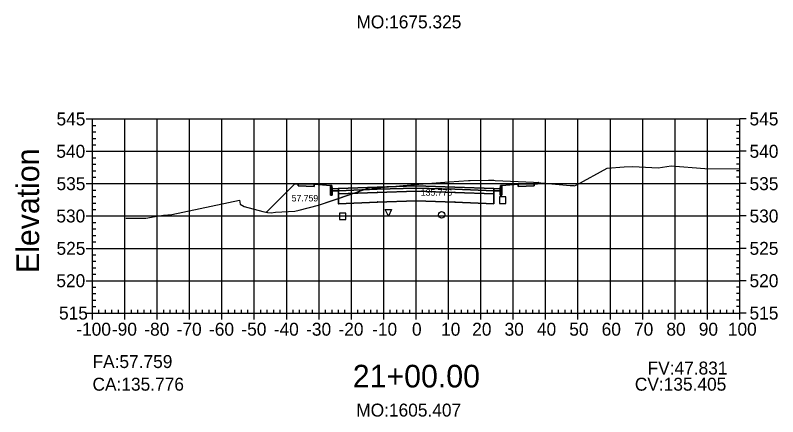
# Model space of a CAD drawing. Extents: x 704834 to 709892, y 372981 to 377533.
# Drawn here: x 705463 to 705698.6, y 373570.8 to 373694.9 of the extents above; entities that cross this region are included whole.
import ezdxf

# ---------------------------------------------------------------- set-up
doc = ezdxf.new("R2010")
doc.units = 0
for name, color, linetype in [('1', 7, 'Continuous'), ('10', 7, 'Continuous'), ('13', 7, 'Continuous'), ('14', 7, 'Continuous'), ('4', 7, 'Continuous'), ('57', 7, 'Continuous'), ('59', 7, 'Continuous'), ('60', 7, 'Continuous'), ('Default_Xsect', 7, 'Continuous'), ('Existing', 7, 'Continuous')]:
    doc.layers.add(name, color=color, linetype=linetype)

msp = doc.modelspace()

# ---------------------------------------------------------------- linework, layer by layer
for points in [[(705549.37, 373642.77), (705540.61, 373634)], [(705550.37, 373642.81), (705549.37, 373642.77)], [(705623.37, 373642.81), (705624.37, 373642.77)], [(705624.37, 373642.77), (705624.76, 373643.16)], [(705560.37, 373642.21), (705555.37, 373642.61)], [(705613.37, 373642.21), (705618.37, 373642.61)]]:
    msp.add_lwpolyline(points)
for points in [[(705555.37, 373642.61), (705550.37, 373642.81), (705550.37, 373642.15), (705555.37, 373641.95)], [(705618.37, 373641.95), (705623.37, 373642.15), (705623.37, 373642.81), (705618.37, 373642.61)], [(705560.87, 373641.21), (705560.79, 373642.21), (705560.37, 373642.21), (705560.37, 373639.21), (705560.87, 373639.21)], [(705562.87, 373641.29), (705560.87, 373641.21), (705560.87, 373640.55), (705562.87, 373640.63)], [(705586.87, 373641.47), (705598.87, 373641.11), (705610.87, 373640.63), (705610.87, 373641.29), (705598.87, 373641.77), (705586.87, 373642.13), (705574.87, 373641.77), (705562.87, 373641.29), (705562.87, 373640.63), (705574.87, 373641.11)], [(705586.87, 373640.47), (705598.87, 373640.11), (705610.87, 373639.63), (705610.87, 373640.63), (705598.87, 373641.11), (705586.87, 373641.47), (705574.87, 373641.11), (705562.87, 373640.63), (705562.87, 373639.63), (705574.87, 373640.11)], [(705586.87, 373637.47), (705598.87, 373637.11), (705610.87, 373636.63), (705610.87, 373639.63), (705598.87, 373640.11), (705586.87, 373640.47), (705574.87, 373640.11), (705562.87, 373639.63), (705562.87, 373636.63), (705574.87, 373637.11)], [(705586.82, 373641.42), (705586.92, 373641.42), (705586.92, 373641.52), (705586.82, 373641.52)], [(705586.82, 373640.42), (705586.92, 373640.42), (705586.92, 373640.52), (705586.82, 373640.52)], [(705610.87, 373640.63), (705612.87, 373640.55), (705612.87, 373641.21), (705610.87, 373641.29)], [(705612.87, 373639.21), (705613.37, 373639.21), (705613.37, 373642.21), (705612.96, 373642.21), (705612.87, 373641.21)], [(705562.82, 373639.58), (705562.92, 373639.58), (705562.92, 373639.68), (705562.82, 373639.68)], [(705574.82, 373640.06), (705574.92, 373640.06), (705574.92, 373640.16), (705574.82, 373640.16)], [(705598.82, 373640.06), (705598.92, 373640.06), (705598.92, 373640.16), (705598.82, 373640.16)], [(705610.82, 373639.58), (705610.92, 373639.58), (705610.92, 373639.68), (705610.82, 373639.68)], [(705562.82, 373636.58), (705562.92, 373636.58), (705562.92, 373636.68), (705562.82, 373636.68)], [(705574.82, 373637.06), (705574.92, 373637.06), (705574.92, 373637.16), (705574.82, 373637.16)], [(705586.82, 373637.42), (705586.92, 373637.42), (705586.92, 373637.52), (705586.82, 373637.52)], [(705598.82, 373637.06), (705598.92, 373637.06), (705598.92, 373637.16), (705598.82, 373637.16)], [(705610.82, 373636.58), (705610.92, 373636.58), (705610.92, 373636.68), (705610.82, 373636.68)]]:
    msp.add_lwpolyline(points, close=True)
at = {"layer": '1'}
for points in [[(705540.61, 373634), (705540.9, 373633.95), (705542.05, 373633.75), (705543.42, 373633.99), (705549.39, 373634.36), (705550.74, 373634.62), (705556.73, 373636.21), (705562.87, 373638.28), (705562.87, 373639.63), (705562.87, 373640.63), (705560.87, 373640.55), (705560.87, 373639.21), (705560.37, 373639.21), (705560.37, 373642.21), (705555.37, 373642.61), (705555.37, 373641.95), (705550.37, 373642.15), (705550.37, 373642.81), (705549.37, 373642.77)], [(705562.87, 373638.28), (705570.86, 373640.97), (705573, 373641.76), (705573.32, 373641.44), (705573.38, 373641.38), (705574.82, 373641.5), (705586.37, 373642.55), (705597.05, 373643.35), (705603.06, 373643.76), (705603.39, 373643.8), (705603.55, 373643.82), (705609.22, 373643.89), (705609.3, 373643.9), (705609.63, 373643.94), (705610.87, 373643.86), (705611.26, 373643.82), (705623.11, 373643.31), (705624.76, 373643.16), (705624.37, 373642.77), (705623.37, 373642.81), (705623.37, 373642.15), (705618.37, 373641.95), (705618.37, 373642.61), (705613.37, 373642.21), (705613.37, 373639.21), (705612.87, 373639.21), (705612.87, 373640.55), (705610.87, 373640.63), (705610.87, 373639.63), (705610.87, 373636.63), (705598.87, 373637.11), (705586.87, 373637.47), (705574.87, 373637.11), (705562.87, 373636.63)], [(705578.29, 373632.81), (705577.29, 373634.81), (705579.29, 373634.81)]]:
    msp.add_lwpolyline(points, close=True, dxfattribs=at)
at = {"layer": '10'}
msp.add_lwpolyline([(705563.16, 373631.72), (705565.16, 373631.72), (705565.16, 373633.72), (705563.16, 373633.72)], close=True, dxfattribs=at)
at = {"layer": '13'}
msp.add_circle((705594.75, 373633.18), 1, dxfattribs=at)
at = {"layer": '14'}
for points in [[(705624.76, 373643.16), (705624.76, 373643.21), (705624.76, 373643.16), (705624.71, 373643.16), (705624.76, 373643.16), (705624.76, 373643.11), (705624.76, 373643.16), (705624.81, 373643.16)], [(705562.87, 373641.29), (705562.87, 373641.34), (705562.87, 373641.29), (705562.82, 373641.29), (705562.87, 373641.29), (705562.87, 373641.24), (705562.87, 373641.29), (705562.92, 373641.29)], [(705574.87, 373641.77), (705574.87, 373641.82), (705574.87, 373641.77), (705574.82, 373641.77), (705574.87, 373641.77), (705574.87, 373641.72), (705574.87, 373641.77), (705574.92, 373641.77)], [(705586.87, 373642.13), (705586.87, 373642.18), (705586.87, 373642.13), (705586.82, 373642.13), (705586.87, 373642.13), (705586.87, 373642.08), (705586.87, 373642.13), (705586.92, 373642.13)], [(705598.87, 373641.77), (705598.87, 373641.82), (705598.87, 373641.77), (705598.82, 373641.77), (705598.87, 373641.77), (705598.87, 373641.72), (705598.87, 373641.77), (705598.92, 373641.77)], [(705610.87, 373641.29), (705610.87, 373641.34), (705610.87, 373641.29), (705610.82, 373641.29), (705610.87, 373641.29), (705610.87, 373641.24), (705610.87, 373641.29), (705610.92, 373641.29)], [(705540.61, 373634), (705540.61, 373634.05), (705540.61, 373634), (705540.56, 373634), (705540.61, 373634), (705540.61, 373633.95), (705540.61, 373634), (705540.66, 373634)]]:
    msp.add_lwpolyline(points, dxfattribs=at)
at = {"layer": '4'}
msp.add_lwpolyline([(705612.61, 373636.72), (705614.61, 373636.72), (705614.61, 373638.72), (705612.61, 373638.72)], close=True, dxfattribs=at)
at = {"layer": '57'}
for p, q in [((705484.87, 373662.82), (705486.87, 373662.82)), ((705486.87, 373662.82), (705686.87, 373662.82)), ((705486.87, 373602.82), (705486.87, 373662.82)), ((705486.87, 373602.82), (705486.87, 373662.82)), ((705496.87, 373602.82), (705496.87, 373662.82)), ((705506.87, 373602.82), (705506.87, 373662.82)), ((705516.87, 373602.82), (705516.87, 373662.82)), ((705526.87, 373602.82), (705526.87, 373662.82)), ((705536.87, 373602.82), (705536.87, 373662.82)), ((705546.87, 373602.82), (705546.87, 373662.82)), ((705556.87, 373602.82), (705556.87, 373662.82)), ((705566.87, 373602.82), (705566.87, 373662.82)), ((705576.87, 373602.82), (705576.87, 373662.82)), ((705586.87, 373602.82), (705586.87, 373662.82)), ((705596.87, 373602.82), (705596.87, 373662.82)), ((705606.87, 373602.82), (705606.87, 373662.82)), ((705616.87, 373602.82), (705616.87, 373662.82)), ((705626.87, 373602.82), (705626.87, 373662.82)), ((705636.87, 373602.82), (705636.87, 373662.82)), ((705646.87, 373602.82), (705646.87, 373662.82)), ((705656.87, 373602.82), (705656.87, 373662.82)), ((705666.87, 373602.82), (705666.87, 373662.82)), ((705676.87, 373602.82), (705676.87, 373662.82)), ((705686.87, 373602.82), (705686.87, 373662.82)), ((705686.87, 373602.82), (705686.87, 373662.82)), ((705688.87, 373662.82), (705686.87, 373662.82)), ((705486.87, 373660.82), (705487.87, 373660.82)), ((705686.87, 373660.82), (705685.87, 373660.82)), ((705486.87, 373658.82), (705487.87, 373658.82)), ((705686.87, 373658.82), (705685.87, 373658.82)), ((705486.87, 373656.82), (705487.87, 373656.82)), ((705486.87, 373654.82), (705487.87, 373654.82)), ((705686.87, 373656.82), (705685.87, 373656.82)), ((705686.87, 373654.82), (705685.87, 373654.82)), ((705484.87, 373652.82), (705486.87, 373652.82)), ((705486.87, 373652.82), (705686.87, 373652.82)), ((705688.87, 373652.82), (705686.87, 373652.82)), ((705486.87, 373650.82), (705487.87, 373650.82)), ((705686.87, 373650.82), (705685.87, 373650.82)), ((705486.87, 373648.82), (705487.87, 373648.82)), ((705686.87, 373648.82), (705685.87, 373648.82)), ((705486.87, 373646.82), (705487.87, 373646.82)), ((705686.87, 373646.82), (705685.87, 373646.82)), ((705484.87, 373642.82), (705486.87, 373642.82)), ((705486.87, 373644.82), (705487.87, 373644.82)), ((705486.87, 373642.82), (705686.87, 373642.82)), ((705686.87, 373644.82), (705685.87, 373644.82)), ((705688.87, 373642.82), (705686.87, 373642.82)), ((705486.87, 373640.82), (705487.87, 373640.82)), ((705686.87, 373640.82), (705685.87, 373640.82)), ((705486.87, 373638.82), (705487.87, 373638.82)), ((705686.87, 373638.82), (705685.87, 373638.82)), ((705486.87, 373636.82), (705487.87, 373636.82)), ((705686.87, 373636.82), (705685.87, 373636.82)), ((705486.87, 373634.82), (705487.87, 373634.82)), ((705686.87, 373634.82), (705685.87, 373634.82)), ((705484.87, 373632.82), (705486.87, 373632.82)), ((705486.87, 373632.82), (705686.87, 373632.82)), ((705688.87, 373632.82), (705686.87, 373632.82)), ((705486.87, 373630.82), (705487.87, 373630.82)), ((705486.87, 373628.82), (705487.87, 373628.82)), ((705686.87, 373630.82), (705685.87, 373630.82)), ((705686.87, 373628.82), (705685.87, 373628.82)), ((705486.87, 373626.82), (705487.87, 373626.82)), ((705686.87, 373626.82), (705685.87, 373626.82)), ((705486.87, 373624.82), (705487.87, 373624.82)), ((705686.87, 373624.82), (705685.87, 373624.82)), ((705484.87, 373622.82), (705486.87, 373622.82)), ((705486.87, 373622.82), (705686.87, 373622.82)), ((705688.87, 373622.82), (705686.87, 373622.82)), ((705486.87, 373620.82), (705487.87, 373620.82)), ((705686.87, 373620.82), (705685.87, 373620.82)), ((705486.87, 373618.82), (705487.87, 373618.82)), ((705686.87, 373618.82), (705685.87, 373618.82)), ((705486.87, 373616.82), (705487.87, 373616.82)), ((705486.87, 373614.82), (705487.87, 373614.82)), ((705686.87, 373616.82), (705685.87, 373616.82)), ((705686.87, 373614.82), (705685.87, 373614.82)), ((705484.87, 373612.82), (705486.87, 373612.82)), ((705486.87, 373612.82), (705686.87, 373612.82)), ((705688.87, 373612.82), (705686.87, 373612.82)), ((705486.87, 373610.82), (705487.87, 373610.82)), ((705686.87, 373610.82), (705685.87, 373610.82)), ((705486.87, 373608.82), (705487.87, 373608.82)), ((705686.87, 373608.82), (705685.87, 373608.82)), ((705486.87, 373606.82), (705487.87, 373606.82)), ((705686.87, 373606.82), (705685.87, 373606.82)), ((705484.87, 373602.82), (705486.87, 373602.82)), ((705486.87, 373604.82), (705487.87, 373604.82)), ((705486.87, 373602.82), (705686.87, 373602.82)), ((705486.87, 373602.82), (705686.87, 373602.82)), ((705486.87, 373600.82), (705486.87, 373602.82)), ((705488.87, 373602.82), (705488.87, 373603.82)), ((705490.87, 373602.82), (705490.87, 373603.82)), ((705492.87, 373602.82), (705492.87, 373603.82)), ((705494.87, 373602.82), (705494.87, 373603.82)), ((705496.87, 373600.82), (705496.87, 373602.82)), ((705498.87, 373602.82), (705498.87, 373603.82)), ((705500.87, 373602.82), (705500.87, 373603.82)), ((705502.87, 373602.82), (705502.87, 373603.82)), ((705504.87, 373602.82), (705504.87, 373603.82)), ((705506.87, 373600.82), (705506.87, 373602.82)), ((705508.87, 373602.82), (705508.87, 373603.82)), ((705510.87, 373602.82), (705510.87, 373603.82)), ((705512.87, 373602.82), (705512.87, 373603.82)), ((705514.87, 373602.82), (705514.87, 373603.82)), ((705516.87, 373600.82), (705516.87, 373602.82)), ((705518.87, 373602.82), (705518.87, 373603.82)), ((705520.87, 373602.82), (705520.87, 373603.82)), ((705522.87, 373602.82), (705522.87, 373603.82)), ((705524.87, 373602.82), (705524.87, 373603.82)), ((705526.87, 373600.82), (705526.87, 373602.82)), ((705528.87, 373602.82), (705528.87, 373603.82)), ((705530.87, 373602.82), (705530.87, 373603.82)), ((705532.87, 373602.82), (705532.87, 373603.82)), ((705534.87, 373602.82), (705534.87, 373603.82)), ((705536.87, 373600.82), (705536.87, 373602.82)), ((705538.87, 373602.82), (705538.87, 373603.82)), ((705540.87, 373602.82), (705540.87, 373603.82)), ((705542.87, 373602.82), (705542.87, 373603.82)), ((705544.87, 373602.82), (705544.87, 373603.82)), ((705546.87, 373600.82), (705546.87, 373602.82)), ((705548.87, 373602.82), (705548.87, 373603.82)), ((705550.87, 373602.82), (705550.87, 373603.82)), ((705552.87, 373602.82), (705552.87, 373603.82)), ((705554.87, 373602.82), (705554.87, 373603.82)), ((705556.87, 373600.82), (705556.87, 373602.82)), ((705558.87, 373602.82), (705558.87, 373603.82)), ((705560.87, 373602.82), (705560.87, 373603.82)), ((705562.87, 373602.82), (705562.87, 373603.82)), ((705564.87, 373602.82), (705564.87, 373603.82)), ((705566.87, 373600.82), (705566.87, 373602.82)), ((705568.87, 373602.82), (705568.87, 373603.82)), ((705570.87, 373602.82), (705570.87, 373603.82)), ((705572.87, 373602.82), (705572.87, 373603.82)), ((705574.87, 373602.82), (705574.87, 373603.82)), ((705576.87, 373600.82), (705576.87, 373602.82)), ((705578.87, 373602.82), (705578.87, 373603.82)), ((705580.87, 373602.82), (705580.87, 373603.82)), ((705582.87, 373602.82), (705582.87, 373603.82)), ((705584.87, 373602.82), (705584.87, 373603.82)), ((705586.87, 373600.82), (705586.87, 373602.82)), ((705588.87, 373602.82), (705588.87, 373603.82)), ((705590.87, 373602.82), (705590.87, 373603.82)), ((705592.87, 373602.82), (705592.87, 373603.82)), ((705594.87, 373602.82), (705594.87, 373603.82)), ((705596.87, 373600.82), (705596.87, 373602.82)), ((705598.87, 373602.82), (705598.87, 373603.82)), ((705600.87, 373602.82), (705600.87, 373603.82)), ((705602.87, 373602.82), (705602.87, 373603.82)), ((705604.87, 373602.82), (705604.87, 373603.82)), ((705606.87, 373600.82), (705606.87, 373602.82)), ((705608.87, 373602.82), (705608.87, 373603.82)), ((705610.87, 373602.82), (705610.87, 373603.82)), ((705612.87, 373602.82), (705612.87, 373603.82)), ((705614.87, 373602.82), (705614.87, 373603.82)), ((705616.87, 373600.82), (705616.87, 373602.82)), ((705618.87, 373602.82), (705618.87, 373603.82)), ((705620.87, 373602.82), (705620.87, 373603.82)), ((705622.87, 373602.82), (705622.87, 373603.82)), ((705624.87, 373602.82), (705624.87, 373603.82)), ((705626.87, 373600.82), (705626.87, 373602.82)), ((705628.87, 373602.82), (705628.87, 373603.82)), ((705630.87, 373602.82), (705630.87, 373603.82)), ((705632.87, 373602.82), (705632.87, 373603.82)), ((705634.87, 373602.82), (705634.87, 373603.82)), ((705636.87, 373600.82), (705636.87, 373602.82)), ((705638.87, 373602.82), (705638.87, 373603.82)), ((705640.87, 373602.82), (705640.87, 373603.82)), ((705642.87, 373602.82), (705642.87, 373603.82)), ((705644.87, 373602.82), (705644.87, 373603.82)), ((705646.87, 373600.82), (705646.87, 373602.82)), ((705648.87, 373602.82), (705648.87, 373603.82)), ((705650.87, 373602.82), (705650.87, 373603.82)), ((705652.87, 373602.82), (705652.87, 373603.82)), ((705654.87, 373602.82), (705654.87, 373603.82)), ((705656.87, 373600.82), (705656.87, 373602.82)), ((705658.87, 373602.82), (705658.87, 373603.82)), ((705660.87, 373602.82), (705660.87, 373603.82)), ((705662.87, 373602.82), (705662.87, 373603.82)), ((705664.87, 373602.82), (705664.87, 373603.82)), ((705666.87, 373600.82), (705666.87, 373602.82)), ((705668.87, 373602.82), (705668.87, 373603.82)), ((705670.87, 373602.82), (705670.87, 373603.82)), ((705672.87, 373602.82), (705672.87, 373603.82)), ((705674.87, 373602.82), (705674.87, 373603.82)), ((705676.87, 373600.82), (705676.87, 373602.82)), ((705678.87, 373602.82), (705678.87, 373603.82)), ((705680.87, 373602.82), (705680.87, 373603.82)), ((705682.87, 373602.82), (705682.87, 373603.82)), ((705684.87, 373602.82), (705684.87, 373603.82)), ((705686.87, 373604.82), (705685.87, 373604.82)), ((705686.87, 373600.82), (705686.87, 373602.82)), ((705688.87, 373602.82), (705686.87, 373602.82))]:
    msp.add_line(p, q, dxfattribs=at)
at = {"layer": 'Default_Xsect'}
msp.add_lwpolyline([(705540.61, 373634), (705549.37, 373642.77), (705550.37, 373642.81), (705555.37, 373642.61), (705560.37, 373642.21), (705560.79, 373642.21), (705560.87, 373641.21), (705562.87, 373641.29), (705574.87, 373641.77), (705586.87, 373642.13), (705598.87, 373641.77), (705610.87, 373641.29), (705612.87, 373641.21), (705612.96, 373642.21), (705613.37, 373642.21), (705618.37, 373642.61), (705623.37, 373642.81), (705624.37, 373642.77), (705624.76, 373643.16)], dxfattribs=at)
at = {"layer": 'Existing'}
msp.add_lwpolyline([(705497.2, 373632.13), (705503.38, 373632.2), (705506.22, 373632.7), (705508.85, 373633.06), (705511.35, 373633.28), (705532.33, 373637.71), (705532.52, 373636.45), (705533.72, 373635.73), (705539.48, 373634.2), (705540.9, 373633.95), (705542.05, 373633.75), (705543.42, 373633.99), (705549.39, 373634.36), (705550.74, 373634.62), (705556.73, 373636.21), (705570.86, 373640.97), (705573, 373641.76), (705573.32, 373641.44), (705573.38, 373641.38), (705574.82, 373641.5), (705586.37, 373642.55), (705597.05, 373643.35), (705603.06, 373643.76), (705603.39, 373643.8), (705603.55, 373643.82), (705609.22, 373643.89), (705609.3, 373643.9), (705609.63, 373643.94), (705610.87, 373643.86), (705611.26, 373643.82), (705623.11, 373643.31), (705634.45, 373642.26), (705634.72, 373642.25), (705635.47, 373642.23), (705635.67, 373642.17), (705636.47, 373642.5), (705645.86, 373647.57), (705651.15, 373648.01), (705653.84, 373648.08), (705661.61, 373647.73), (705665.61, 373648.37), (705676.08, 373647.5), (705686.87, 373647.44)], dxfattribs=at)

# ---------------------------------------------------------------- texts
for s, p in [('CA:135.776', (705486.87, 373578.82)), ('CV:135.405', (705654.44, 373578.82))]:
    msp.add_text(s, height=4).set_placement(p)
at = {"layer": '1'}
msp.add_text('21+00.00', height=7, dxfattribs=at).set_placement((705567.28, 373579.82))
at = {"layer": '14'}
for p in [(705550.34, 373642.76), (705623.34, 373642.76), (705550.34, 373642.1), (705555.34, 373641.9), (705618.34, 373641.9), (705623.34, 373642.1)]:
    msp.add_text('+', height=0.1, dxfattribs=at).set_placement(p)
at = {"layer": '57'}
for s, p in [('545', (705475.75, 373660.82)), ('545', (705689.87, 373660.82)), ('540', (705475.7, 373650.82)), ('540', (705689.87, 373650.82)), ('535', (705475.75, 373640.82)), ('535', (705689.87, 373640.82)), ('530', (705475.7, 373630.82)), ('530', (705689.87, 373630.82)), ('525', (705475.75, 373620.82)), ('525', (705689.87, 373620.82)), ('520', (705475.7, 373610.82)), ('520', (705689.87, 373610.82)), ('515', (705476.52, 373600.82)), ('515', (705689.87, 373600.82)), ('-100', (705481.86, 373595.82)), ('-90', (705492.87, 373595.82)), ('-80', (705502.87, 373595.82)), ('-70', (705512.87, 373595.82)), ('-60', (705522.87, 373595.82)), ('-50', (705532.87, 373595.82)), ('-40', (705542.87, 373595.82)), ('-30', (705552.87, 373595.82)), ('-20', (705562.87, 373595.82)), ('-10', (705573.26, 373595.82)), ('0', (705585.58, 373595.82)), ('10', (705594.57, 373595.82)), ('20', (705604.18, 373595.82)), ('30', (705614.18, 373595.82)), ('40', (705624.18, 373595.82)), ('50', (705634.18, 373595.82)), ('60', (705644.18, 373595.82)), ('70', (705654.18, 373595.82)), ('80', (705664.18, 373595.82)), ('90', (705674.18, 373595.82)), ('100', (705683.17, 373595.82))]:
    msp.add_text(s, height=4, dxfattribs=at).set_placement(p)
at = {"layer": '59'}
for s, height, p in [('MO:1675.325', 4, (705568.42, 373690.82)), ('135.776', 2, (705588.31, 373639.09)), ('57.759', 2, (705548.41, 373637.32)), ('FA:57.759', 4, (705486.87, 373585.82)), ('FV:47.831', 4, (705658.37, 373583.82)), ('MO:1605.407', 4, (705568.36, 373570.82))]:
    msp.add_text(s, height=height, dxfattribs=at).set_placement(p)
at = {"layer": '60'}
msp.add_text('Elevation', height=7, rotation=90, dxfattribs=at).set_placement((705470.37, 373615.18))

doc.saveas('drawing.dxf')
